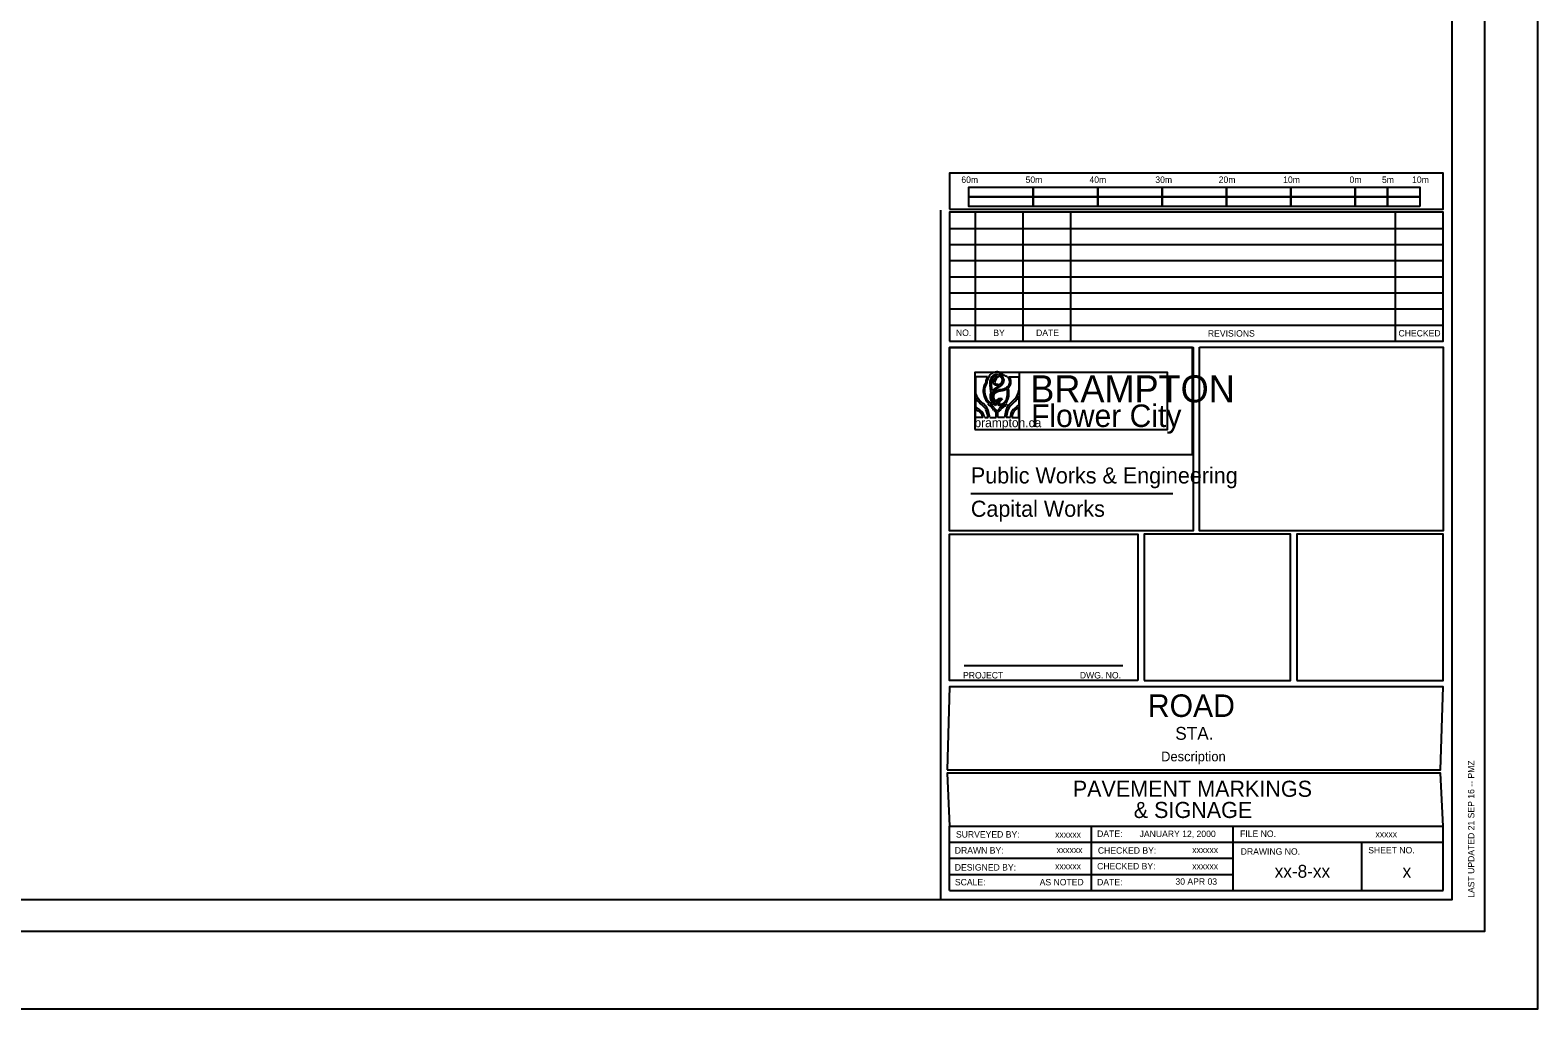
# Model space of a CAD drawing. Extents: x 595568 to 603631, y 4837996 to 4846716.
# Drawn here: x 603142.9 to 603377, y 4846340.6 to 4846492.6 of the extents above; entities that cross this region are included whole.
import ezdxf

# ---------------------------------------------------------------- set-up
doc = ezdxf.new("R2010")
doc.units = 0
for name, color, linetype in [('-PRINT FULLSIZE', 7, 'Continuous'), ('-PRINT HALFSIZE', 7, 'Continuous'), ('ENG_BORDER', 7, 'Continuous'), ('ENG_KEY', 7, 'Continuous'), ('ENG_LOGO', 7, 'Continuous'), ('ENG_TITLEBLOCK', 7, 'Continuous'), ('ENG_TX_BORDER', 7, 'Continuous'), ('ENG_TX_KEY', 7, 'Continuous'), ('ENG_TX_LOGO', 7, 'Continuous'), ('ENG_TX_TITLE-DESC', 7, 'Continuous'), ('ENG_TX_TITLEBLOCK', 7, 'Continuous'), ('ENG_WK_MISC-2', 7, 'Continuous')]:
    doc.layers.add(name, color=color, linetype=linetype)

msp = doc.modelspace()

# ---------------------------------------------------------------- linework, layer by layer
at = {"layer": '-PRINT FULLSIZE'}
msp.add_lwpolyline([(602930, 4846340.65), (603377.03, 4846340.65), (603377.03, 4846645.65), (602930, 4846645.65)], close=True, dxfattribs=at)
at = {"layer": '-PRINT HALFSIZE'}
msp.add_lwpolyline([(602959.8, 4846631.64), (603368.72, 4846631.64), (603368.72, 4846352.64), (602959.8, 4846352.64)], close=True, dxfattribs=at)
at = {"layer": 'ENG_BORDER'}
msp.add_line((603284.31, 4846357.64), (603284.31, 4846464.61), dxfattribs=at)
msp.add_lwpolyline([(602975.52, 4846357.64), (603363.72, 4846357.64), (603363.72, 4846626.64), (602975.52, 4846626.64)], close=True, dxfattribs=at)
at = {"layer": 'ENG_KEY'}
for points in [[(603285.69, 4846464.8), (603362.31, 4846464.8), (603362.31, 4846470.39), (603285.69, 4846470.39)], [(603298.68, 4846466.72), (603288.68, 4846466.72), (603288.68, 4846468.22), (603298.68, 4846468.22)], [(603298.68, 4846465.22), (603288.68, 4846465.22), (603288.68, 4846466.72), (603298.68, 4846466.72)], [(603308.68, 4846466.72), (603298.68, 4846466.72), (603298.68, 4846468.22), (603308.68, 4846468.22)], [(603308.68, 4846465.22), (603298.68, 4846465.22), (603298.68, 4846466.72), (603308.68, 4846466.72)], [(603318.68, 4846466.72), (603308.68, 4846466.72), (603308.68, 4846468.22), (603318.68, 4846468.22)], [(603318.68, 4846465.22), (603308.68, 4846465.22), (603308.68, 4846466.72), (603318.68, 4846466.72)], [(603328.68, 4846466.72), (603318.68, 4846466.72), (603318.68, 4846468.22), (603328.68, 4846468.22)], [(603328.68, 4846465.22), (603318.68, 4846465.22), (603318.68, 4846466.72), (603328.68, 4846466.72)], [(603338.68, 4846466.72), (603328.68, 4846466.72), (603328.68, 4846468.22), (603338.68, 4846468.22)], [(603338.68, 4846465.22), (603328.68, 4846465.22), (603328.68, 4846466.72), (603338.68, 4846466.72)], [(603348.68, 4846466.72), (603338.68, 4846466.72), (603338.68, 4846468.22), (603348.68, 4846468.22)], [(603348.68, 4846465.22), (603338.68, 4846465.22), (603338.68, 4846466.72), (603348.68, 4846466.72)], [(603353.68, 4846466.72), (603348.68, 4846466.72), (603348.68, 4846468.22), (603353.68, 4846468.22)], [(603353.68, 4846465.22), (603348.68, 4846465.22), (603348.68, 4846466.72), (603353.68, 4846466.72)], [(603358.68, 4846466.72), (603353.68, 4846466.72), (603353.68, 4846468.22), (603358.68, 4846468.22)], [(603358.68, 4846465.22), (603353.68, 4846465.22), (603353.68, 4846466.72), (603358.68, 4846466.72)]]:
    msp.add_lwpolyline(points, close=True, dxfattribs=at)
at = {"layer": 'ENG_LOGO'}
for p, q in [((603291.59, 4846438.78), (603289.69, 4846438.78)), ((603289.69, 4846438.78), (603289.69, 4846436.55)), ((603294.87, 4846438.78), (603296.45, 4846438.78)), ((603296.45, 4846438.78), (603296.45, 4846436.69)), ((603292.1, 4846436.53), (603291.98, 4846437.48)), ((603292.28, 4846436.61), (603292.13, 4846437.81)), ((603293.36, 4846437.42), (603292.28, 4846436.61)), ((603293.45, 4846437.25), (603292.37, 4846436.44)), ((603289.69, 4846435.53), (603289.69, 4846434.15)), ((603291.94, 4846434.73), (603292.31, 4846434.73)), ((603292.75, 4846434.49), (603292.75, 4846434.59)), ((603293.93, 4846434.23), (603294.32, 4846434.6)), ((603296.45, 4846435.73), (603296.45, 4846434.4)), ((603296.45, 4846432.45), (603296.45, 4846434.03)), ((603289.69, 4846432.45), (603289.69, 4846433.78)), ((603290.87, 4846432.45), (603289.69, 4846432.45)), ((603291.14, 4846432.45), (603291.65, 4846432.45)), ((603291.91, 4846432.45), (603292.9, 4846432.45)), ((603292.9, 4846432.45), (603292.9, 4846433.31)), ((603293.16, 4846432.45), (603293.16, 4846433.27)), ((603294.21, 4846432.45), (603293.16, 4846432.45)), ((603295.09, 4846432.45), (603294.48, 4846432.45)), ((603295.34, 4846432.45), (603296.45, 4846432.45))]:
    msp.add_line(p, q, dxfattribs=at)
for centre, major_axis, start_param, end_param in [((603292.63, 4846437.83), (0, 1.57), 0.915828, 1.568717), ((603293.06, 4846437.61), (0, 1.92), 5.678233, 7.807497), ((603293.02, 4846437.83), (0, -1.29), 3.318986, 4.976585), ((603292.72, 4846438.47), (0, 0.423), 0.666047, 1.576027), ((603293.98, 4846437.43), (0, 1.86), 0.628774, 1.255965), ((603292.93, 4846438), (0, 0.951), 6.118882, 6.855525), ((603294.04, 4846437.35), (0, 1.73), 0.484278, 1.276713), ((603292.96, 4846438.11), (0, 0.995), 5.937042, 6.443816), ((603293.86, 4846437.3), (0, 1.9), 6.209925, 6.677582), ((603293.17, 4846437.98), (0, 0.932), 5.514665, 6.02559), ((603293.87, 4846437.57), (0, 1.44), 6.104016, 6.552384), ((603293.36, 4846438.01), (0, 0.978), 5.100192, 6.058655), ((603293.47, 4846438.2), (0, 0.536), 4.934552, 5.720905), ((603293.74, 4846436.93), (0, 2.1), 5.705811, 6.088794), ((603294.28, 4846437.96), (0, 0.893), 4.747453, 5.681752), ((603294.51, 4846438.07), (0, 0.833), 4.858966, 5.733736), ((603291.18, 4846436.68), (0, -1.79), 4.785712, 5.370532), ((603292.46, 4846436.54), (0, 1.86), 1.493845, 2.002346), ((603292.24, 4846436.68), (0, 1.59), 0.764321, 1.571722), ((603293.12, 4846436.69), (0, 2.42), 1.555738, 2.522651), ((603292.2, 4846436.72), (0, 1.32), 0.74139, 1.563754), ((603293.36, 4846435.78), (0, 1.64), 1.184297, 2.265825), ((603291.88, 4846437.46), (0, -0.13), 1.717889, 1.834992), ((603291.89, 4846436.5), (0, 0.259), 4.32589, 4.859481), ((603292.99, 4846437.92), (0, 1.03), 1.119551, 1.674398), ((603292.7, 4846435.9), (0, 0.673), 0.63706, 1.540523), ((603293.23, 4846438.42), (0, -1.22), 4.758696, 4.974719), ((603292.61, 4846438.23), (0, -0.454), 4.989814, 5.515803), ((603292.8, 4846438.39), (0, 0.526), 1.423327, 2.376918), ((603293.28, 4846438.93), (0, -1.51), 5.455385, 6.346676), ((603293.08, 4846435.61), (0, 0.963), 0.28455, 1.028854), ((603293.04, 4846435.75), (0, 0.62), 0.179588, 1.425103), ((603293.21, 4846438.61), (0, -1), 5.558935, 6.198642), ((603294.4, 4846431.68), (0, 5.19), 0.207106, 0.364997), ((603294.11, 4846432.81), (0, 3.81), 0.147367, 0.372097), ((603293.28, 4846438.47), (0, -0.881), 6.098575, 6.969537), ((603292.71, 4846439.02), (0, -1.97), 0.460861, 0.945922), ((603292.27, 4846445.86), (0, -9.21), 0.161819, 0.267812), ((603292.57, 4846443.68), (0, -7.22), 0.177455, 0.344982), ((603293.34, 4846438.27), (0, -0.677), 0.785512, 1.640949), ((603293.5, 4846438.24), (0, 0.761), 4.195874, 4.894963), ((603293.88, 4846438.4), (0, -1.51), 0.344201, 0.831804), ((603293.29, 4846436.07), (0, -1.9), 0.78097, 1.623824), ((603292.75, 4846436.21), (0, 2.33), 4.273394, 5.005808), ((603293.97, 4846438.32), (0, -1.6), 0.654188, 1.084874), ((603292.14, 4846436.18), (0, -3.28), 1.565289, 1.83996), ((603294.45, 4846437.92), (0, 0.697), 3.823835, 4.807307), ((603293.68, 4846438.04), (0, -1.82), 1.316711, 1.656268), ((603294.67, 4846437.01), (0, -2.14), 0.712478, 1.421371), ((603291.63, 4846437.05), (0, -2.78), 5.292666, 5.605077), ((603292.96, 4846439.2), (0, -6.39), 5.623762, 5.757196), ((603292.82, 4846438.2), (0, -4.27), 5.369755, 5.566262), ((603292.46, 4846437.85), (0, -4.03), 5.537119, 5.75381), ((603335.94, 4846507.05), (0, -90.24), 5.63745, 5.644913), ((603289.41, 4846432.14), (0, 2.75), 5.320654, 5.659535), ((603290.29, 4846433.17), (0, 1.6), 5.416876, 5.78378), ((603292.88, 4846436.56), (0, -2.33), 5.06368, 5.674398), ((603289.87, 4846432.61), (0, 2.34), 5.018027, 5.462353), ((603292.04, 4846433.78), (0, 0.938), 0.365522, 0.597805), ((603290.48, 4846431.99), (0, 2.89), 5.439641, 5.800947), ((603292.06, 4846432.33), (0, 2.2), 5.823202, 6.334077), ((603289.95, 4846430.9), (0, 4.35), 5.482733, 5.697338), ((603293.63, 4846435.88), (0, -1.78), 4.68622, 4.981796), ((603293.61, 4846435.94), (0, -1.78), 5.019488, 5.665896), ((603284.51, 4846424.95), (0, 12.9), 5.441321, 5.480214), ((603293.46, 4846435.69), (0, 1.35), 1.258524, 1.853874), ((603293.68, 4846435.77), (0, -1.63), 4.995413, 5.526463), ((603293.21, 4846435.63), (0, 0.845), 1.326911, 2.090694), ((603293.48, 4846434.8), (0, -1.39), 5.382989, 5.704264), ((603293.54, 4846435.71), (0, -1.23), 5.131028, 5.477302), ((603293.54, 4846434.39), (0, 1.01), 5.87892, 7.368381), ((603293.56, 4846434.43), (0, -0.828), 3.173377, 4.865507), ((603293.39, 4846434.62), (0, 0.273), 1.287529, 2.899642), ((603293.87, 4846434.49), (0, 0.861), 0.477744, 1.324571), ((603291.65, 4846435.42), (0, -2.66), 0.828888, 0.938456), ((603293.58, 4846435.08), (0, -0.775), 5.896411, 6.466099), ((603293.54, 4846434.69), (0, 0.193), 0.693494, 2.795441), ((603294.59, 4846433.87), (0, 1.68), 0.532188, 0.957727), ((603293.79, 4846433.66), (0, 0.445), 0.214109, 1.153309), ((603293.58, 4846435.9), (0, -1.39), 6.206413, 6.519617), ((603294.07, 4846433.25), (0, 0.72), 0.422403, 0.821661), ((603292.97, 4846437.68), (0, -3.48), 0.25264, 0.48256), ((603293.06, 4846435.97), (0, -2.02), 0.390063, 0.537232), ((603292.96, 4846436.29), (0, -2.6), 0.408149, 0.566756), ((603293.29, 4846436.12), (0, -1.71), 0.401305, 1.020747), ((603292.2, 4846437.04), (0, -3.74), 0.664019, 0.865631), ((603294.22, 4846433.96), (0, 0.792), 5.695616, 5.978543), ((603296.02, 4846433.01), (0, 1.97), 0.6523, 1.336939), ((603296.65, 4846432.45), (0, 2.56), 0.690534, 1.157714), ((603276.65, 4846462.29), (0, -35.35), 0.669806, 0.705808), ((603286.42, 4846449.27), (0, -18.23), 0.619451, 0.667551), ((603296.57, 4846432.42), (0, 1.73), 0.445246, 0.869293), ((603297.42, 4846431.43), (0, 2.85), 0.417687, 0.818457), ((603294.19, 4846437.42), (0, -3.18), 0.682687, 1.010528), ((603291.25, 4846442.66), (0, -10.34), 0.573803, 0.643743), ((603292.15, 4846438.13), (0, -5.26), 5.687848, 5.809574), ((603289.49, 4846431.89), (0, 1.75), 5.497917, 5.817483), ((603288.7, 4846430.56), (0, 3.64), 5.540505, 5.738863), ((603289.43, 4846431.87), (0, 1.81), 5.039091, 5.480629), ((603289.47, 4846431.82), (0, 2.1), 5.021624, 5.458474), ((603289.53, 4846432.31), (0, 2.53), 4.76812, 5.296774), ((603289.15, 4846432.12), (0, 3.31), 4.811691, 5.079969), ((603293.04, 4846434.03), (0, -0.731), 5.423199, 6.055208), ((603293.07, 4846433.96), (0, -0.427), 5.581796, 6.941571), ((603292.89, 4846434.25), (0, -1.03), 0.32402, 1.048968), ((603298.33, 4846431.78), (0, 4.97), 1.223572, 1.434629), ((603301.37, 4846430.99), (0, 8.37), 1.268607, 1.395258), ((603296.53, 4846432.37), (0, 1.73), 0.824174, 1.519908), ((603297.1, 4846432.09), (0, 2.14), 0.923116, 1.39853)]:
    msp.add_ellipse(centre, major_axis=major_axis, ratio=0.837209, start_param=start_param, end_param=end_param, dxfattribs=at)
at = {"layer": 'ENG_TITLEBLOCK'}
for p, q in [((603289.69, 4846444.3), (603289.69, 4846464.3)), ((603297.11, 4846444.3), (603297.11, 4846464.3)), ((603304.51, 4846444.3), (603304.51, 4846464.3)), ((603354.91, 4846444.3), (603354.91, 4846464.3)), ((603285.69, 4846461.8), (603362.31, 4846461.8)), ((603285.69, 4846459.3), (603362.31, 4846459.3)), ((603285.69, 4846456.8), (603362.31, 4846456.8)), ((603285.69, 4846454.3), (603362.31, 4846454.3)), ((603285.69, 4846451.8), (603362.31, 4846451.8)), ((603285.69, 4846449.3), (603362.31, 4846449.3)), ((603285.69, 4846446.8), (603362.31, 4846446.8)), ((603288.99, 4846420.64), (603320.37, 4846420.64)), ((603287.95, 4846393.94), (603312.57, 4846393.94)), ((603285.69, 4846359.01), (603285.69, 4846369.01)), ((603285.69, 4846369.01), (603362.31, 4846369.01)), ((603307.71, 4846359.01), (603307.71, 4846369.01)), ((603329.71, 4846359.01), (603329.71, 4846369.01)), ((603362.31, 4846359.01), (603362.31, 4846369.01)), ((603285.69, 4846366.51), (603362.31, 4846366.51)), ((603349.71, 4846359.01), (603349.71, 4846366.51)), ((603285.69, 4846364.01), (603329.71, 4846364.01)), ((603285.69, 4846361.51), (603329.71, 4846361.51)), ((603285.69, 4846359.01), (603362.31, 4846359.01))]:
    msp.add_line(p, q, dxfattribs=at)
for points in [[(603285.69, 4846444.3), (603362.31, 4846444.3), (603362.31, 4846464.3), (603285.69, 4846464.3)], [(603285.69, 4846443.3), (603323.5, 4846443.3), (603323.5, 4846414.83), (603285.69, 4846414.83)], [(603324.5, 4846443.36), (603362.31, 4846443.36), (603362.31, 4846414.83), (603324.5, 4846414.83)], [(603314.91, 4846391.63), (603285.69, 4846391.63), (603285.69, 4846414.33), (603314.91, 4846414.33)], [(603315.91, 4846391.63), (603338.61, 4846391.63), (603338.61, 4846414.33), (603315.91, 4846414.33)], [(603339.61, 4846391.63), (603362.31, 4846391.63), (603362.31, 4846414.33), (603339.61, 4846414.33)], [(603285.3, 4846377.75), (603361.92, 4846377.75), (603362.31, 4846390.63), (603285.69, 4846390.63)], [(603285.69, 4846369.01), (603362.31, 4846369.01), (603361.92, 4846377.25), (603285.3, 4846377.25)]]:
    msp.add_lwpolyline(points, close=True, dxfattribs=at)
at = {"layer": 'ENG_WK_MISC-2'}
for points in [[(603285.69, 4846426.71), (603323.4, 4846426.71), (603323.4, 4846443.33), (603285.69, 4846443.33)], [(603289.58, 4846430.6), (603319.51, 4846430.6), (603319.51, 4846439.45), (603289.58, 4846439.45)], [(603289.58, 4846430.6), (603296.56, 4846430.6), (603296.56, 4846439.45), (603289.58, 4846439.45)]]:
    msp.add_lwpolyline(points, close=True, dxfattribs=at)

# ---------------------------------------------------------------- texts
at = {"layer": 'ENG_TX_BORDER'}
for s, height, rotation, p in [('ROAD', 3.5, 360, (603316.47, 4846385.96)), ('STA.', 2, 360, (603320.72, 4846382.41)), ('Description', 1.5, 360, (603318.53, 4846379.07)), ('LAST UPDATED 21 SEP 16 -- PMZ', 1, 90, (603367.17, 4846357.88)), ('xx-8-xx', 2, 360, (603336.16, 4846361)), ('x', 2, 360, (603356.02, 4846361))]:
    msp.add_text(s, height=height, rotation=rotation, dxfattribs=at).set_placement(p)
at = {"layer": 'ENG_TX_KEY'}
for s, p in [('60m', (603287.51, 4846468.86)), ('50m', (603297.48, 4846468.86)), ('40m', (603307.4, 4846468.86)), ('30m', (603317.63, 4846468.86)), ('20m', (603327.47, 4846468.86)), ('10m', (603337.48, 4846468.86)), ('0m', (603347.79, 4846468.86)), ('5m', (603352.82, 4846468.86)), ('10m', (603357.5, 4846468.86))]:
    msp.add_text(s, height=1, dxfattribs=at).set_placement(p)
at = {"layer": 'ENG_TX_LOGO'}
msp.add_text('brampton.ca', height=1.3968, rotation=0.002, dxfattribs=at).set_placement((603289.54, 4846430.94))
at = {"layer": 'ENG_TX_TITLE-DESC'}
for s, p in [('PAVEMENT MARKINGS', (603304.81, 4846373.56)), ('& SIGNAGE', (603314.28, 4846370.27))]:
    msp.add_text(s, height=2.5, rotation=360, dxfattribs=at).set_placement(p)
at = {"layer": 'ENG_TX_TITLEBLOCK'}
for s, height, rotation, p in [('NO.', 1, 360, (603286.67, 4846445.1)), ('BY', 1, 360, (603292.47, 4846445.1)), ('DATE', 1, 360, (603299.11, 4846445.1)), ('REVISIONS', 1, 360, (603325.79, 4846445)), ('CHECKED', 1, 360, (603355.39, 4846445.02)), ('BRAMPTON', 4.191, 0.0021, (603298.21, 4846434.8)), ('Flower City', 3.4921, 0.0021, (603298.33, 4846430.97)), ('Public Works & Engineering', 2.5, 0.0021, (603288.99, 4846422.2)), ('Capital Works', 2.5, 0.0021, (603288.99, 4846417.03)), ('PROJECT', 1, 360, (603287.77, 4846391.93)), ('DWG. NO.', 1, 360, (603305.91, 4846391.93)), ('SURVEYED BY:            ', 1, 360, (603286.67, 4846367.23)), ('DATE:', 1, 360, (603308.59, 4846367.33)), ('JANUARY 12, 2000', 1, 360, (603315.19, 4846367.31)), ('FILE NO.', 1, 360, (603330.79, 4846367.33)), ('xxxxxx', 1, 360, (603302.07, 4846367.22)), ('xxxxx', 1, 360, (603351.82, 4846367.27)), ('DRAWN BY:              ', 1, 360, (603286.49, 4846364.75)), ('xxxxxx', 1, 360, (603302.3, 4846364.82)), ('CHECKED BY:', 1, 360, (603308.71, 4846364.73)), ('xxxxxx', 1, 360, (603323.36, 4846364.83)), ('DRAWING NO.', 1, 360, (603330.89, 4846364.57)), ('SHEET NO.', 1, 360, (603350.69, 4846364.77)), ('DESIGNED BY:', 1, 360, (603286.49, 4846362.11)), ('xxxxxx', 1, 360, (603302.07, 4846362.3)), ('CHECKED BY:', 1, 360, (603308.59, 4846362.29)), ('xxxxxx', 1, 360, (603323.36, 4846362.3)), ('SCALE:', 1, 360, (603286.51, 4846359.81)), ('AS NOTED', 1, 360, (603299.67, 4846359.81)), ('DATE:', 1, 360, (603308.59, 4846359.81)), ('30 APR 03', 1, 360, (603320.75, 4846359.91))]:
    msp.add_text(s, height=height, rotation=rotation, dxfattribs=at).set_placement(p)

doc.saveas('drawing.dxf')
